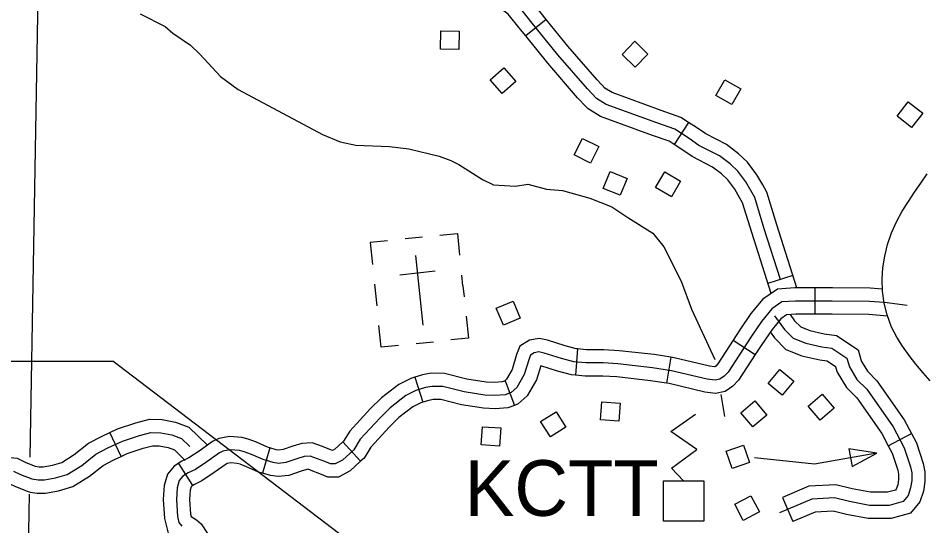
# Model space of a CAD drawing. Extents: x 1370130 to 1380143, y 377636 to 380256.
# Drawn here: x 1377248.1 to 1377392.9, y 379363.5 to 379444.4 of the extents above; entities that cross this region are included whole.
import ezdxf

# ---------------------------------------------------------------- set-up
doc = ezdxf.new("R2010")
doc.units = 0
for name, color, linetype in [('Level 10', 7, 'Continuous'), ('Level 32', 7, 'Continuous'), ('Level 35', 7, 'Continuous'), ('Level 45', 7, 'Continuous'), ('Level 5', 7, 'Continuous'), ('Level 56', 7, 'Continuous'), ('Level 57', 7, 'Continuous'), ('R_Draft', 7, 'Continuous')]:
    doc.layers.add(name, color=color, linetype=linetype)

msp = doc.modelspace()

# ---------------------------------------------------------------- linework, layer by layer
at = {"layer": 'Level 10'}
for p, q in [((1377392.11, 379418.12), (1377393.13, 379419.62)), ((1377391.11, 379416.66), (1377392.11, 379418.12)), ((1377390.12, 379415.19), (1377391.11, 379416.66)), ((1377389.13, 379413.62), (1377390.12, 379415.19)), ((1377388.21, 379411.93), (1377389.13, 379413.62)), ((1377387.43, 379410.16), (1377388.21, 379411.93)), ((1377386.8, 379408.35), (1377387.43, 379410.16)), ((1377386.34, 379406.49), (1377386.8, 379408.35)), ((1377386.07, 379404.63), (1377386.34, 379406.49)), ((1377385.95, 379402.78), (1377386.07, 379404.63)), ((1377385.99, 379400.9), (1377385.95, 379402.78)), ((1377386.24, 379398.96), (1377385.99, 379400.9)), ((1377386.72, 379397.09), (1377386.24, 379398.96)), ((1377387.42, 379395.16), (1377386.72, 379397.09)), ((1377388.3, 379393.56), (1377387.42, 379395.16)), ((1377389.2, 379392.1), (1377388.3, 379393.56)), ((1377390.23, 379390.6), (1377389.2, 379392.1)), ((1377391.33, 379389.23), (1377390.23, 379390.6)), ((1377392.46, 379387.88), (1377391.33, 379389.23)), ((1377393.62, 379386.56), (1377392.46, 379387.88))]:
    msp.add_line(p, q, dxfattribs=at)
at = {"layer": 'Level 32'}
for p, q in [((1377375.19, 379401.4), (1377375.19, 379397.2)), ((1377362.16, 379393.05), (1377365.68, 379390.76)), ((1377337.35, 379391.66), (1377337.02, 379387.47)), ((1377352.22, 379390.34), (1377351.56, 379386.19)), ((1377311.39, 379387.18), (1377312.65, 379383.17)), ((1377325.8, 379386.6), (1377327.27, 379382.67)), ((1377299.91, 379376.84), (1377302.74, 379373.75)), ((1377288.25, 379375.89), (1377287.11, 379371.85)), ((1377273.67, 379373.4), (1377275.94, 379369.87))]:
    msp.add_line(p, q, dxfattribs=at)
for points in [[(1377375.19, 379401.4), (1377372.02, 379401.4), (1377369.22, 379401.22), (1377366.9, 379399.6), (1377365.01, 379397.31), (1377363.22, 379394.69), (1377362.16, 379393.05)], [(1377385.95, 379401.19), (1377384.02, 379401.36), (1377377.99, 379401.4), (1377375.19, 379401.4)], [(1377389.94, 379398.61), (1377386.33, 379399.05), (1377383.93, 379399.26), (1377377.98, 379399.3), (1377372.09, 379399.3), (1377369.94, 379399.16), (1377368.33, 379398.04), (1377366.69, 379396.05), (1377364.97, 379393.53), (1377361.38, 379387.99), (1377360.76, 379387.32), (1377360.05, 379386.84), (1377359.28, 379386.68), (1377358.02, 379386.84), (1377352.35, 379388.19), (1377349.28, 379388.68), (1377343.79, 379389.29), (1377341.45, 379389.45), (1377338.66, 379389.45), (1377336.76, 379389.6), (1377334.77, 379390.15), (1377332.04, 379391.01), (1377331.18, 379391.2), (1377330.44, 379391.07), (1377329.85, 379390.69), (1377329.61, 379390.09), (1377328.85, 379387.57), (1377327.68, 379385.52), (1377326.76, 379384.72), (1377325.78, 379384.35), (1377324.15, 379384.23), (1377322.56, 379384.29), (1377319.27, 379384.81), (1377315.84, 379385.67), (1377314.15, 379385.7), (1377313.11, 379385.52), (1377311.54, 379385.03), (1377309.95, 379384.23), (1377307.46, 379382.3), (1377305.84, 379380.7), (1377302.68, 379377.27), (1377301.66, 379375.6), (1377299.85, 379373.95), (1377298.69, 379373.33), (1377297.92, 379373.33), (1377297.03, 379373.69), (1377295.89, 379374.15), (1377294.7, 379374.59), (1377293.75, 379374.53), (1377292.58, 379374.16), (1377290.83, 379373.55), (1377289.64, 379373.42), (1377288.81, 379373.55), (1377287.18, 379374.01), (1377285.34, 379374.84), (1377284.18, 379375.27), (1377283.41, 379375.48), (1377281.94, 379375.6), (1377280.77, 379375.39), (1377280.22, 379375.11), (1377278.19, 379373.67), (1377276.38, 379372.44), (1377275.25, 379371.92), (1377274.39, 379371.37), (1377273.81, 379370.66), (1377273.47, 379369.53), (1377273.35, 379367.68), (1377273.53, 379364.95), (1377273.77, 379364), (1377274.21, 379363.4)], [(1377375.19, 379397.2), (1377372.16, 379397.2), (1377370.66, 379397.11), (1377369.77, 379396.48), (1377368.37, 379394.78), (1377366.72, 379392.37), (1377365.68, 379390.76)], [(1377386.78, 379396.9), (1377383.83, 379397.16), (1377377.97, 379397.2), (1377375.19, 379397.2)], [(1377337.35, 379391.66), (1377337.13, 379391.68), (1377335.36, 379392.17), (1377332.57, 379393.05), (1377331.23, 379393.33), (1377329.66, 379393.07), (1377328.15, 379392.09), (1377327.63, 379390.79), (1377326.9, 379388.41), (1377326.03, 379386.87), (1377325.67, 379386.55), (1377325.8, 379386.6)], [(1377362.16, 379393.05), (1377359.71, 379389.28), (1377359.38, 379388.92), (1377359.22, 379388.81), (1377359.2, 379388.81), (1377358.39, 379388.91), (1377352.76, 379390.25), (1377352.22, 379390.34)], [(1377352.22, 379390.34), (1377349.56, 379390.76), (1377343.97, 379391.39), (1377341.52, 379391.55), (1377338.75, 379391.55), (1377337.35, 379391.66)], [(1377365.68, 379390.76), (1377363.04, 379386.69), (1377362.13, 379385.72), (1377360.88, 379384.86), (1377359.36, 379384.56), (1377357.65, 379384.77), (1377351.94, 379386.13), (1377351.56, 379386.19)], [(1377337.02, 379387.47), (1377336.39, 379387.52), (1377334.17, 379388.14), (1377331.5, 379388.98), (1377331.47, 379388.99), (1377330.79, 379386.74), (1377329.33, 379384.17), (1377327.85, 379382.89), (1377327.27, 379382.67)], [(1377311.39, 379387.18), (1377310.75, 379386.98), (1377308.82, 379386.01), (1377306.08, 379383.88), (1377304.33, 379382.16), (1377301, 379378.54), (1377300.03, 379376.95), (1377299.91, 379376.84)], [(1377325.8, 379386.6), (1377325.32, 379386.42), (1377324.11, 379386.33), (1377322.76, 379386.38), (1377319.69, 379386.87), (1377316.11, 379387.77), (1377313.98, 379387.81), (1377312.61, 379387.56), (1377311.39, 379387.18)], [(1377351.56, 379386.19), (1377349, 379386.6), (1377343.6, 379387.2), (1377341.39, 379387.35), (1377338.58, 379387.35), (1377337.02, 379387.47)], [(1377327.27, 379382.67), (1377326.23, 379382.28), (1377324.19, 379382.13), (1377322.35, 379382.2), (1377318.85, 379382.75), (1377315.56, 379383.58), (1377314.31, 379383.6), (1377313.61, 379383.47), (1377312.65, 379383.17)], [(1377312.65, 379383.17), (1377312.33, 379383.07), (1377311.07, 379382.44), (1377308.85, 379380.71), (1377307.35, 379379.24), (1377304.37, 379376), (1377303.3, 379374.25), (1377302.74, 379373.75)], [(1377288.25, 379375.89), (1377287.9, 379375.99), (1377286.14, 379376.78), (1377284.82, 379377.26), (1377283.78, 379377.56), (1377281.83, 379377.72), (1377280.1, 379377.4), (1377279.13, 379376.92), (1377276.99, 379375.39), (1377275.35, 379374.28), (1377274.24, 379373.77), (1377272.98, 379372.96)], [(1377299.91, 379376.84), (1377298.63, 379375.68), (1377298.24, 379375.47), (1377297.81, 379375.64), (1377296.65, 379376.11), (1377295.01, 379376.71), (1377293.36, 379376.61), (1377291.92, 379376.15), (1377290.37, 379375.61), (1377289.68, 379375.54), (1377289.25, 379375.6), (1377288.25, 379375.89)], [(1377287.11, 379371.85), (1377286.46, 379372.03), (1377284.55, 379372.89), (1377283.53, 379373.27), (1377283.03, 379373.4), (1377282.04, 379373.49), (1377281.44, 379373.38), (1377281.3, 379373.31), (1377279.39, 379371.94), (1377277.42, 379370.61), (1377276.26, 379370.07), (1377275.8, 379369.78)], [(1377302.74, 379373.75), (1377301.07, 379372.21), (1377299.21, 379371.23), (1377297.51, 379371.23), (1377296.24, 379371.74), (1377295.13, 379372.19), (1377294.39, 379372.47), (1377294.14, 379372.45), (1377293.25, 379372.17), (1377291.29, 379371.48), (1377289.59, 379371.31), (1377288.37, 379371.49), (1377287.11, 379371.85)], [(1377272.98, 379372.96), (1377271.91, 379371.67), (1377271.39, 379369.9), (1377271.24, 379367.68), (1377271.45, 379364.62), (1377272.05, 379362.29), (1377274.02, 379361.02), (1377274.14, 379360.92), (1377274.32, 379360.66), (1377274.69, 379358.14), (1377278.84, 379358.75)], [(1377275.8, 379369.78), (1377275.7, 379369.65), (1377275.55, 379369.15), (1377275.45, 379367.68), (1377275.61, 379365.29), (1377275.7, 379364.94), (1377276.54, 379364.4), (1377277.28, 379363.76), (1377278.33, 379362.25), (1377278.84, 379358.75)]]:
    msp.add_lwpolyline(points, dxfattribs=at)
at = {"layer": 'Level 35'}
for points in [[(1377267.55, 379445.13), (1377271.54, 379443.09), (1377272.81, 379442.01), (1377275.61, 379440.12), (1377277.12, 379438.69), (1377280.4, 379435.11), (1377283.19, 379433.02), (1377296.67, 379425.85), (1377299.48, 379424.69), (1377301.98, 379424.19), (1377307.33, 379423.97), (1377310.45, 379423.57), (1377315.27, 379422.43), (1377317.14, 379421.74), (1377318.42, 379421.11), (1377322.2, 379418.67), (1377323.96, 379417.86), (1377327.43, 379417.65), (1377329.41, 379417.95), (1377332.39, 379417.14), (1377334.95, 379416.93), (1377339.28, 379415.7), (1377342.83, 379414.32), (1377345.39, 379412.64), (1377349.37, 379410.14), (1377351.12, 379407.96), (1377353.89, 379402.46), (1377355.53, 379398), (1377359.22, 379389.99)], [(1377360.2, 379384.41), (1377360.77, 379380.89)]]:
    msp.add_lwpolyline(points, dxfattribs=at)
at = {"layer": 'Level 45'}
for p, q in [((1377332.34, 379444.23), (1377329.08, 379441.59)), ((1377355.05, 379427.8), (1377352.77, 379424.27)), ((1377371.71, 379403.39), (1377367.7, 379402.12)), ((1377264.53, 379374.53), (1377262.76, 379378.34)), ((1377386.9, 379376.24), (1377390.61, 379378.2)), ((1377370.06, 379368), (1377371.7, 379364.13))]:
    msp.add_line(p, q, dxfattribs=at)
for points in [[(1377332.34, 379444.23), (1377331.54, 379445.22), (1377329.21, 379448.14), (1377327.98, 379449.02), (1377326.47, 379449.94), (1377324.9, 379450.4), (1377322.67, 379450.7), (1377318.34, 379451.05), (1377318.27, 379451.05)], [(1377329.08, 379441.59), (1377328.27, 379442.59), (1377326.3, 379445.06), (1377325.66, 379445.52), (1377324.75, 379446.07), (1377324.03, 379446.28), (1377322.23, 379446.52), (1377318.1, 379446.85), (1377318.12, 379446.85)], [(1377369.71, 379402.76), (1377367.14, 379410.85), (1377365.61, 379415.82), (1377364.17, 379418.3), (1377362.89, 379420.04), (1377361.68, 379421.19), (1377360, 379422.46), (1377356.71, 379424.14), (1377355.17, 379425.22), (1377352.88, 379426.7), (1377349.99, 379427.71), (1377341.93, 379430.67), (1377340.39, 379431.61), (1377338.91, 379433.15), (1377334.21, 379438.6), (1377329.91, 379443.91), (1377327.76, 379446.6)], [(1377341.83, 379433.13), (1377340.46, 379434.57), (1377335.82, 379439.94), (1377332.34, 379444.23)], [(1377338.8, 379430.23), (1377337.35, 379431.74), (1377332.59, 379437.25), (1377329.08, 379441.59)], [(1377355.05, 379427.8), (1377353.81, 379428.6), (1377350.7, 379429.68), (1377342.85, 379432.57), (1377341.71, 379433.26), (1377341.83, 379433.13)], [(1377352.77, 379424.27), (1377351.95, 379424.8), (1377349.29, 379425.73), (1377341.02, 379428.76), (1377339.06, 379429.96), (1377338.8, 379430.23)], [(1377366.88, 379417.82), (1377365.93, 379419.45), (1377364.48, 379421.44), (1377363.04, 379422.79), (1377361.13, 379424.25), (1377357.79, 379425.95), (1377356.34, 379426.96), (1377355.05, 379427.8)], [(1377363.25, 379415.71), (1377362.41, 379417.15), (1377361.31, 379418.65), (1377360.32, 379419.58), (1377358.88, 379420.68), (1377355.63, 379422.34), (1377354, 379423.48), (1377352.77, 379424.27)], [(1377372.34, 379401.4), (1377369.15, 379411.48), (1377367.55, 379416.67), (1377366.88, 379417.82)], [(1377368.21, 379400.52), (1377365.14, 379410.23), (1377363.68, 379414.97), (1377363.25, 379415.71)], [(1377368.77, 379396.97), (1377370.37, 379394.78), (1377371.76, 379393.39), (1377373.75, 379392.59), (1377376.34, 379392), (1377377.93, 379391.8), (1377380.32, 379390.2), (1377380.71, 379388.81), (1377381.91, 379386.82), (1377383.5, 379385.23), (1377387.68, 379379.25), (1377389.47, 379375.87), (1377390.46, 379372.88), (1377390.66, 379371.89), (1377390.66, 379370.69), (1377390.46, 379369.5), (1377390.07, 379368.3), (1377389.27, 379367.31), (1377387.08, 379366.71), (1377383.9, 379366.71), (1377380.71, 379367.31), (1377378.33, 379367.9), (1377374.74, 379367.7), (1377369.57, 379365.51)], [(1377371.25, 379397.14), (1377371.97, 379396.15), (1377372.94, 379395.18), (1377374.38, 379394.6), (1377376.7, 379394.07), (1377378.68, 379393.82), (1377382.12, 379391.52), (1377382.56, 379389.98)], [(1377368.05, 379394.4), (1377368.76, 379393.42), (1377370.58, 379391.6), (1377373.12, 379390.58), (1377375.97, 379389.93), (1377377.17, 379389.77), (1377378.51, 379388.89), (1377378.52, 379388.83)], [(1377382.56, 379389.98), (1377382.66, 379389.65), (1377383.58, 379388.12), (1377385.11, 379386.58), (1377389.47, 379380.35), (1377390.61, 379378.2)], [(1377378.52, 379388.83), (1377378.77, 379387.97), (1377380.24, 379385.52), (1377381.88, 379383.87), (1377385.88, 379378.16), (1377386.9, 379376.24)], [(1377262.76, 379378.34), (1377263.97, 379378.91), (1377266.88, 379379.88), (1377269.06, 379380.46), (1377271.08, 379380.39), (1377273.19, 379380), (1377275.33, 379379.19), (1377278.3, 379376.32)], [(1377247.38, 379372.18), (1377248.5, 379371.64), (1377250.27, 379370.95), (1377251.29, 379370.78), (1377252.31, 379370.78), (1377254.08, 379371.11), (1377255.95, 379371.64), (1377258.26, 379373.09), (1377260.51, 379374.86), (1377262.44, 379375.88), (1377264.75, 379376.95), (1377267.48, 379377.86), (1377269.3, 379378.35), (1377270.86, 379378.29), (1377272.62, 379377.97), (1377274.18, 379377.38), (1377275.48, 379376.13)], [(1377250.83, 379372.98), (1377251.46, 379372.88), (1377252.12, 379372.88), (1377253.6, 379373.15), (1377255.09, 379373.58), (1377257.05, 379374.81), (1377259.36, 379376.63), (1377261.51, 379377.76), (1377262.76, 379378.34)], [(1377390.61, 379378.2), (1377391.41, 379376.7), (1377392.5, 379373.42), (1377392.76, 379372.09), (1377392.76, 379370.52), (1377392.51, 379368.99), (1377391.94, 379367.28), (1377390.48, 379365.46), (1377387.36, 379364.61), (1377385.2, 379364.61)], [(1377264.53, 379374.53), (1377265.52, 379375), (1377268.08, 379375.85), (1377269.54, 379376.24), (1377270.63, 379376.2), (1377272.06, 379375.94), (1377273.03, 379375.57), (1377274.77, 379373.89)], [(1377386.9, 379376.24), (1377387.53, 379375.04), (1377388.43, 379372.34), (1377388.56, 379371.68), (1377388.56, 379370.86), (1377388.42, 379370), (1377388.19, 379369.32), (1377388.06, 379369.15), (1377386.8, 379368.81), (1377385.2, 379368.81)], [(1377236.41, 379370.37), (1377236.83, 379370.46), (1377238.85, 379371.54), (1377240.28, 379372.61), (1377242.08, 379373.79), (1377244.64, 379374.26), (1377246.39, 379374.39), (1377247.96, 379374.23), (1377249.34, 379373.57), (1377250.83, 379372.98)], [(1377250.05, 379368.85), (1377251.13, 379368.68), (1377252.5, 379368.68), (1377254.56, 379369.06), (1377256.82, 379369.71), (1377259.47, 379371.37), (1377261.66, 379373.09), (1377263.37, 379374), (1377264.53, 379374.53)], [(1377237.35, 379366.27), (1377238.31, 379366.49), (1377241.11, 379367.99), (1377242.69, 379369.17), (1377243.67, 379369.81), (1377245.18, 379370.09), (1377246.33, 379370.18), (1377246.8, 379370.13), (1377247.67, 379369.72), (1377249.72, 379368.91), (1377250.05, 379368.85)], [(1377385.2, 379368.81), (1377384.09, 379368.81), (1377381.16, 379369.36), (1377378.53, 379370.02), (1377374.26, 379369.78), (1377370.06, 379368)], [(1377385.2, 379364.61), (1377383.7, 379364.61), (1377380.26, 379365.25), (1377378.12, 379365.79), (1377375.23, 379365.63), (1377371.7, 379364.13)]]:
    msp.add_lwpolyline(points, dxfattribs=at)
at = {"layer": 'Level 5'}
for points in [[(1377251.74, 379475.59), (1377249.98, 379374.42)], [(1377249.88, 379368.5), (1377249.15, 379326.83)]]:
    msp.add_lwpolyline(points, dxfattribs=at)
at = {"layer": 'Level 56'}
for points in [[(1377318.45, 379442.34), (1377318.39, 379439.43), (1377315.46, 379439.5), (1377315.53, 379442.41)], [(1377346.49, 379440.73), (1377348.58, 379438.7), (1377346.55, 379436.6), (1377344.45, 379438.63)], [(1377325.58, 379436.52), (1377327.52, 379434.34), (1377325.34, 379432.39), (1377323.4, 379434.57)], [(1377360.86, 379434.61), (1377363.39, 379433.17), (1377361.95, 379430.63), (1377359.41, 379432.07)], [(1377392.41, 379429.28), (1377390.61, 379426.98), (1377388.31, 379428.78), (1377390.1, 379431.08)], [(1377338.13, 379425.25), (1377340.73, 379423.93), (1377339.41, 379421.32), (1377336.81, 379422.64)], [(1377345.26, 379418.87), (1377344.15, 379416.17), (1377341.45, 379417.28), (1377342.56, 379419.98)], [(1377351.27, 379419.91), (1377353.79, 379418.45), (1377352.32, 379415.92), (1377349.8, 379417.39)], [(1377324.38, 379398.16), (1377327.06, 379399.3), (1377328.2, 379396.6), (1377325.52, 379395.47)], [(1377367.76, 379386.15), (1377369.61, 379388.39), (1377371.86, 379386.54), (1377370.01, 379384.29)], [(1377378.28, 379382.21), (1377376.06, 379380.32), (1377374.16, 379382.55), (1377376.38, 379384.43)], [(1377341, 379380.34), (1377341.21, 379383.25), (1377344.13, 379383.03), (1377343.92, 379380.13)], [(1377363.41, 379381.5), (1377365.65, 379383.37), (1377367.52, 379381.12), (1377365.29, 379379.25)], [(1377333.02, 379377.63), (1377331.45, 379380.08), (1377333.91, 379381.66), (1377335.48, 379379.2)], [(1377321.98, 379376.36), (1377322.19, 379379.27), (1377325.1, 379379.06), (1377324.9, 379376.15)], [(1377361.06, 379375.38), (1377363.81, 379376.33), (1377364.76, 379373.56), (1377362.01, 379372.62)], [(1377380.62, 379375.72), (1377381.13, 379372.91), (1377385.09, 379375.07)], [(1377362.41, 379366.89), (1377364.99, 379368.26), (1377366.36, 379365.67), (1377363.78, 379364.31)]]:
    msp.add_lwpolyline(points, close=True, dxfattribs=at)
msp.add_lwpolyline([(1377385.09, 379375.07), (1377375.14, 379373.28), (1377365.59, 379374.28)], dxfattribs=at)
at = {"layer": 'Level 57'}
for p, q in [((1377312.62, 379409.52), (1377309.84, 379409.22)), ((1377311.51, 379406.58), (1377312.68, 379395.45)), ((1377309.02, 379403.51), (1377314.61, 379404.1)), ((1377319.06, 379401.75), (1377318.88, 379403.46)), ((1377304.95, 379402), (1377305.32, 379398.52)), ((1377312.1, 379401.02), (1377312.1, 379401.02)), ((1377312.1, 379401.02), (1377312.1, 379401.02)), ((1377319.06, 379401.75), (1377319.24, 379399.98)), ((1377311.6, 379392.52), (1377314.38, 379392.81))]:
    msp.add_line(p, q, dxfattribs=at)
for points in [[(1377315.39, 379409.81), (1377318.18, 379410.1), (1377318.54, 379406.62)], [(1377307.04, 379408.93), (1377304.25, 379408.64), (1377304.62, 379405.15)], [(1377319.57, 379396.88), (1377319.94, 379393.39), (1377317.15, 379393.1)], [(1377308.8, 379392.22), (1377306.01, 379391.93), (1377305.65, 379395.41)], [(1377354.25, 379370.63), (1377352.34, 379372.63), (1377356.36, 379375.65), (1377352.22, 379378.48), (1377356.18, 379381.26)]]:
    msp.add_lwpolyline(points, dxfattribs=at)
msp.add_lwpolyline([(1377351.04, 379364.21), (1377351.04, 379370.63), (1377357.47, 379370.63), (1377357.47, 379364.21)], close=True, dxfattribs=at)
at = {"layer": 'R_Draft'}
for points in [[(1377067.57, 379389.71), (1377263.22, 379389.71)], [(1377365.85, 379311.52), (1377263.22, 379389.71)]]:
    msp.add_lwpolyline(points, dxfattribs=at)

# ---------------------------------------------------------------- texts
at = {"layer": 'Level 57'}
msp.add_text('KCTT', height=8.87, dxfattribs=at).set_placement((1377319.35, 379365.05))

doc.saveas('drawing.dxf')
